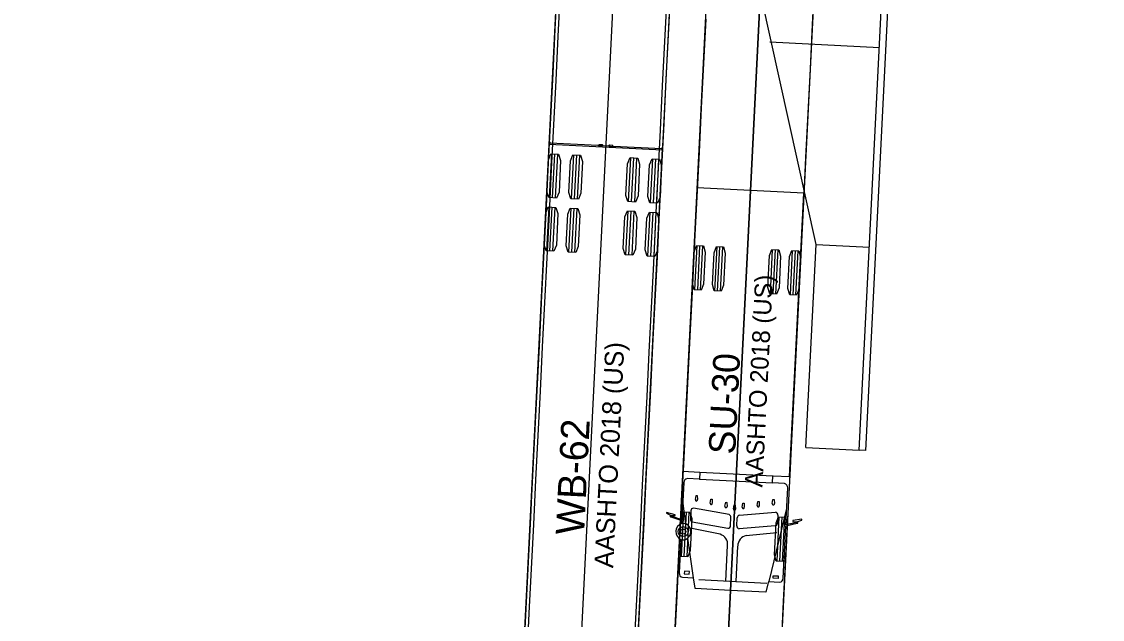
# Model space of a CAD drawing. Extents: x 260275 to 261282, y 610916 to 614143.
# Drawn here: x 260986.2 to 261067.3, y 611972 to 612016.8 of the extents above; entities that cross this region are included whole.
import ezdxf

# ---------------------------------------------------------------- set-up
doc = ezdxf.new("R2010")
doc.units = 0
for name, color, linetype in [('GE_X_Alignment', 7, 'Continuous'), ('PV_P_Curb', 7, 'Continuous'), ('PV_P_EOP', 7, 'Continuous'), ('PV_P_Joint', 7, 'Continuous'), ('UT_X_Water_Cells', 7, 'Continuous')]:
    doc.layers.add(name, color=color, linetype=linetype)

msp = doc.modelspace()

# ---------------------------------------------------------------- linework, layer by layer
at = {"layer": 'GE_X_Alignment'}
msp.add_line((260986.249, 610915.954), (261148.276, 614142.838), dxfattribs=at)
at = {"layer": 'PV_P_Curb'}
for p, q in [((261049.53, 611984.642), (261053.627, 612066.228)), ((261049.53, 611984.641), (261049.031, 611984.667))]:
    msp.add_line(p, q, dxfattribs=at)
at = {"layer": 'PV_P_EOP'}
for p, q in [((261045.801, 612000.096), (261031.212, 612066.209)), ((261049.031, 611984.667), (261053.122, 612066.147)), ((261045.036, 611984.867), (261045.801, 612000.096)), ((261045.036, 611984.867), (261049.031, 611984.667))]:
    msp.add_line(p, q, dxfattribs=at)
at = {"layer": 'PV_P_Joint'}
for p, q in [((261042.339, 612015.289), (261050.548, 612014.877)), ((261045.801, 612000.096), (261049.796, 611999.896))]:
    msp.add_line(p, q, dxfattribs=at)
at = {"layer": 'UT_X_Water_Cells'}
for p, q in [((261044.031, 612066.726), (261023.69, 611661.632)), ((261031.95, 612045.486), (261010.925, 611626.741)), ((261025.794, 612007.621), (261034.283, 612007.195)), ((261025.822, 612003.606), (261025.987, 612006.901)), ((261026.051, 612003.594), (261026.216, 612006.89)), ((261026.279, 612003.583), (261026.445, 612006.878)), ((261029.511, 612007.505), (261029.777, 612007.492)), ((261030.301, 612007.465), (261029.779, 612007.491)), ((261030.042, 612007.478), (261030.039, 612007.408)), ((261030.307, 612007.465), (261030.573, 612007.452)), ((261027.47, 612003.523), (261027.635, 612006.819)), ((261027.699, 612003.511), (261027.864, 612006.807)), ((261027.927, 612003.5), (261028.093, 612006.796)), ((261031.748, 612003.308), (261031.913, 612006.604)), ((261031.976, 612003.297), (261032.142, 612006.592)), ((261032.205, 612003.285), (261032.371, 612006.581)), ((261033.395, 612003.225), (261033.561, 612006.521)), ((261033.624, 612003.214), (261033.79, 612006.51)), ((261033.853, 612003.202), (261034.019, 612006.498)), ((261025.621, 611999.611), (261025.787, 612002.906)), ((261025.85, 611999.599), (261026.015, 612002.895)), ((261026.079, 611999.588), (261026.244, 612002.883)), ((261027.269, 611999.528), (261027.435, 612002.824)), ((261027.498, 611999.516), (261027.663, 612002.812)), ((261027.727, 611999.505), (261027.892, 612002.801)), ((261031.547, 611999.313), (261031.712, 612002.609)), ((261031.776, 611999.302), (261031.941, 612002.597)), ((261032.005, 611999.29), (261032.17, 612002.586)), ((261033.195, 611999.23), (261033.36, 612002.526)), ((261033.424, 611999.219), (261033.589, 612002.515)), ((261033.653, 611999.207), (261033.818, 612002.503)), ((261036.718, 611996.685), (261036.885, 612000.014)), ((261036.926, 611996.674), (261037.093, 612000.003)), ((261037.134, 611996.664), (261037.301, 611999.993)), ((261038.216, 611996.609), (261038.383, 611999.939)), ((261038.424, 611996.599), (261038.591, 611999.928)), ((261038.632, 611996.589), (261038.799, 611999.918)), ((261042.377, 611996.4), (261042.544, 611999.73)), ((261042.585, 611996.39), (261042.752, 611999.719)), ((261042.793, 611996.38), (261042.96, 611999.709)), ((261043.875, 611996.325), (261044.042, 611999.654)), ((261044.083, 611996.315), (261044.25, 611999.644)), ((261044.291, 611996.304), (261044.458, 611999.633)), ((261037.079, 611983.029), (261042.564, 611982.754)), ((261037.052, 611982.499), (261042.537, 611982.223)), ((261036.761, 611980.971), (261036.812, 611981.269)), ((261036.812, 611981.269), (261036.895, 611981.265)), ((261036.895, 611981.265), (261036.916, 611980.964)), ((261037.867, 611980.705), (261037.918, 611981.003)), ((261037.918, 611981.003), (261038, 611980.999)), ((261038, 611980.999), (261038.021, 611980.698)), ((261042.519, 611980.682), (261042.57, 611980.98)), ((261042.57, 611980.98), (261042.653, 611980.976)), ((261042.653, 611980.976), (261042.674, 611980.675)), ((261035.806, 611980.683), (261036.022, 611979.149)), ((261036.413, 611980.133), (261036.382, 611979.517)), ((261039.278, 611979.839), (261036.605, 611980.326)), ((261038.973, 611980.467), (261039.024, 611980.765)), ((261039.024, 611980.765), (261039.107, 611980.761)), ((261039.107, 611980.761), (261039.127, 611980.459)), ((261039.612, 611980.267), (261039.663, 611980.564)), ((261039.663, 611980.564), (261039.746, 611980.56)), ((261039.746, 611980.56), (261039.766, 611980.259)), ((261040.268, 611980.402), (261040.319, 611980.7)), ((261040.319, 611980.7), (261040.401, 611980.696)), ((261040.401, 611980.696), (261040.422, 611980.394)), ((261041.393, 611980.514), (261041.444, 611980.826)), ((261041.444, 611980.826), (261041.526, 611980.822)), ((261041.526, 611980.822), (261041.547, 611980.507)), ((261043.596, 611980.292), (261042.255, 611974.824)), ((261035.715, 611976.71), (261035.882, 611980.039)), ((261035.923, 611976.699), (261036.09, 611980.029)), ((261036.131, 611976.689), (261036.298, 611980.018)), ((261039.389, 611979.014), (261039.42, 611979.63)), ((261039.864, 611978.99), (261039.894, 611979.606)), ((261040.056, 611979.8), (261042.765, 611980.016)), ((261042.872, 611976.35), (261043.039, 611979.68)), ((261042.936, 611979.805), (261042.905, 611979.189)), ((261043.08, 611976.34), (261043.247, 611979.669)), ((261043.288, 611976.33), (261043.455, 611979.659)), ((261038.611, 611978.364), (261036.356, 611978.824)), ((261036.524, 611979.308), (261039.197, 611978.821)), ((261042.743, 611978.995), (261040.035, 611978.779)), ((261035.67, 611977.984), (261035.544, 611975.465)), ((261036.173, 611978.074), (261036.592, 611975.109)), ((261040.572, 611978.265), (261042.85, 611978.496)), ((261039.035, 611974.863), (261039.169, 611977.528)), ((261039.8, 611974.824), (261039.933, 611977.489)), ((261035.926, 611975.598), (261035.917, 611975.404)), ((261035.917, 611975.404), (261036.295, 611975.385)), ((261036.304, 611975.579), (261035.926, 611975.598)), ((261036.295, 611975.385), (261036.304, 611975.579)), ((261037.001, 611974.965), (261042.099, 611974.709)), ((261042.578, 611975.07), (261042.588, 611975.264)), ((261042.957, 611975.051), (261042.578, 611975.07)), ((261042.588, 611975.264), (261042.966, 611975.245)), ((261042.966, 611975.245), (261042.957, 611975.051))]:
    msp.add_line(p, q, dxfattribs=at)
for points in [[(261009.34, 611680.102), (261030.965, 612110.617), (261039.455, 612110.191), (261039.447, 612110.045), (261039.447, 612110.045)], [(261039.447, 612110.045), (261018.12, 611685.301)], [(261020.965, 611687.133), (261041.34, 612092.893), (261049.33, 612092.492), (261049.322, 612092.345), (261049.322, 612092.345)], [(261049.322, 612092.345), (261028.546, 611678.469)], [(261045.686, 612019.927), (261045.519, 612016.599), (261045.352, 612013.27), (261045.185, 612009.942), (261045.018, 612006.613), (261044.85, 612003.284), (261044.683, 611999.956), (261044.516, 611996.627), (261044.349, 611993.298), (261044.182, 611989.97), (261044.015, 611986.641), (261043.848, 611983.313), (261043.68, 611979.984), (261043.513, 611976.655), (261043.346, 611973.327), (261043.179, 611969.998)], [(261045.686, 612019.924), (261045.519, 612016.596), (261045.352, 612013.267), (261045.184, 612009.938), (261045.017, 612006.61), (261044.85, 612003.281), (261044.683, 611999.953), (261044.516, 611996.624), (261044.349, 611993.295), (261044.182, 611989.967), (261044.015, 611986.638), (261043.847, 611983.309), (261043.68, 611979.981), (261043.513, 611976.652), (261043.346, 611973.324), (261043.179, 611969.995)], [(261026.394, 612019.578), (261026.227, 612016.249), (261026.06, 612012.921), (261025.893, 612009.592), (261025.726, 612006.263), (261025.559, 612002.935), (261025.391, 611999.606), (261025.224, 611996.277), (261025.057, 611992.949), (261024.89, 611989.62), (261024.723, 611986.291), (261024.556, 611982.963), (261024.389, 611979.634), (261024.221, 611976.305), (261024.054, 611972.977), (261023.887, 611969.648)], [(261026.618, 612019.057), (261026.451, 612015.729), (261026.284, 612012.4), (261026.117, 612009.071), (261025.95, 612005.743), (261025.783, 612002.414), (261025.616, 611999.085), (261025.448, 611995.757), (261025.281, 611992.428), (261025.114, 611989.099), (261024.947, 611985.771), (261024.78, 611982.442), (261024.613, 611979.113), (261024.446, 611975.785), (261024.279, 611972.456), (261024.111, 611969.127)], [(261034.884, 612019.152), (261034.716, 612015.823), (261034.549, 612012.494), (261034.382, 612009.166), (261034.215, 612005.837), (261034.048, 612002.508), (261033.881, 611999.18), (261033.714, 611995.851), (261033.546, 611992.522), (261033.379, 611989.194), (261033.212, 611985.865), (261033.045, 611982.536), (261032.878, 611979.208), (261032.711, 611975.879), (261032.544, 611972.55), (261032.376, 611969.222)], [(261034.608, 612018.656), (261034.441, 612015.327), (261034.274, 612011.999), (261034.107, 612008.67), (261033.94, 612005.341), (261033.773, 612002.013), (261033.606, 611998.684), (261033.438, 611995.355), (261033.271, 611992.027), (261033.104, 611988.698), (261032.937, 611985.369), (261032.77, 611982.041), (261032.603, 611978.712), (261032.436, 611975.384), (261032.268, 611972.055), (261032.101, 611968.726)], [(261037.529, 612017), (261037.362, 612013.671), (261037.195, 612010.343), (261037.028, 612007.014), (261036.86, 612003.685), (261036.693, 612000.357), (261036.526, 611997.028), (261036.359, 611993.7), (261036.192, 611990.371), (261036.025, 611987.042), (261035.858, 611983.714), (261035.69, 611980.385), (261035.523, 611977.056), (261035.356, 611973.728), (261035.189, 611970.399)], [(261037.529, 612016.997), (261037.362, 612013.668), (261037.195, 612010.34), (261037.027, 612007.011), (261036.86, 612003.682), (261036.693, 612000.354), (261036.526, 611997.025), (261036.359, 611993.696), (261036.192, 611990.368), (261036.025, 611987.039), (261035.857, 611983.711), (261035.69, 611980.382), (261035.523, 611977.053), (261035.356, 611973.725), (261035.189, 611970.396)], [(261025.82, 612007.69), (261025.797, 612007.691), (261023.394, 611959.822), (261027.638, 611959.609), (261031.883, 611959.396), (261034.287, 612007.265), (261034.264, 612007.266)], [(261029.782, 612007.562), (261029.516, 612007.575), (261029.515, 612007.575), (261029.511, 612007.505), (261029.476, 612007.507), (261025.845, 612007.689), (261025.844, 612007.689)], [(261034.24, 612007.268), (261034.239, 612007.267), (261030.608, 612007.45), (261030.573, 612007.452), (261030.576, 612007.522), (261030.575, 612007.522), (261030.309, 612007.535)], [(261043.435, 611982.178), (261042.54, 611982.223), (261042.537, 611982.227), (261042.564, 611982.753), (261042.575, 611982.753), (261043.816, 611982.691), (261044.884, 612003.951), (261040.889, 612004.152), (261036.894, 612004.352), (261035.826, 611983.092), (261037.068, 611983.03), (261037.079, 611983.029), (261037.052, 611982.502), (261037.049, 611982.499), (261036.154, 611982.544)], [(261035.884, 611982.241), (261035.745, 611979.471), (261035.739, 611979.459), (261034.934, 611979.719), (261034.934, 611979.719)], [(261044.367, 611979.246), (261044.366, 611979.246), (261043.539, 611979.067), (261043.535, 611979.08), (261043.674, 611981.85)], [(261034.924, 611979.74), (261034.925, 611979.784), (261034.926, 611979.785), (261035.243, 611979.777), (261035.246, 611979.777), (261035.249, 611979.833), (261035.246, 611979.834), (261034.597, 611980.006), (261034.595, 611980.007), (261034.591, 611979.942), (261034.879, 611979.795), (261034.88, 611979.795), (261034.878, 611979.748)], [(261034.915, 611979.673), (261034.916, 611979.673), (261035.735, 611979.405), (261035.741, 611979.393), (261035.729, 611979.165)], [(261044.425, 611979.268), (261044.428, 611979.315), (261044.428, 611979.316), (261044.73, 611979.433), (261044.733, 611979.497), (261044.73, 611979.497), (261044.068, 611979.391), (261044.065, 611979.39), (261044.062, 611979.335), (261044.065, 611979.334), (261044.381, 611979.31), (261044.382, 611979.309), (261044.379, 611979.265)], [(261043.334, 611975.074), (261043.531, 611979.002), (261043.538, 611979.013), (261044.38, 611979.198), (261044.381, 611979.197)], [(261035.782, 611975.149), (261036.588, 611975.109), (261036.592, 611975.104), (261036.702, 611974.326), (261036.744, 611974.322), (261039.384, 611974.189), (261042.025, 611974.057), (261042.067, 611974.057), (261042.254, 611974.82), (261042.259, 611974.824), (261043.065, 611974.784)]]:
    msp.add_lwpolyline(points, dxfattribs=at)
for points in [[(261026.336, 612003.58), (261025.765, 612003.608), (261025.616, 612004.078), (261025.735, 612006.451), (261025.93, 612006.904), (261026.502, 612006.876), (261026.651, 612006.405), (261026.532, 612004.032)], [(261027.984, 612003.497), (261027.413, 612003.526), (261027.264, 612003.996), (261027.383, 612006.369), (261027.578, 612006.821), (261028.15, 612006.793), (261028.299, 612006.323), (261028.179, 612003.95)], [(261032.262, 612003.282), (261031.691, 612003.311), (261031.542, 612003.781), (261031.661, 612006.154), (261031.856, 612006.607), (261032.428, 612006.578), (261032.577, 612006.108), (261032.457, 612003.735)], [(261033.91, 612003.199), (261033.339, 612003.228), (261033.19, 612003.698), (261033.309, 612006.071), (261033.504, 612006.524), (261034.076, 612006.495), (261034.224, 612006.025), (261034.105, 612003.652)], [(261026.136, 611999.585), (261025.564, 611999.613), (261025.415, 612000.083), (261025.535, 612002.456), (261025.73, 612002.909), (261026.301, 612002.881), (261026.45, 612002.411), (261026.331, 612000.038)], [(261027.784, 611999.502), (261027.212, 611999.531), (261027.063, 612000.001), (261027.182, 612002.374), (261027.378, 612002.827), (261027.949, 612002.798), (261028.098, 612002.328), (261027.979, 611999.955)], [(261032.061, 611999.287), (261031.49, 611999.316), (261031.341, 611999.786), (261031.46, 612002.159), (261031.656, 612002.612), (261032.227, 612002.583), (261032.376, 612002.113), (261032.257, 611999.74)], [(261033.709, 611999.204), (261033.138, 611999.233), (261032.989, 611999.703), (261033.108, 612002.076), (261033.304, 612002.529), (261033.875, 612002.5), (261034.024, 612002.03), (261033.905, 611999.657)], [(261037.185, 611996.661), (261036.666, 611996.687), (261036.533, 611997.161), (261036.653, 611999.558), (261036.833, 612000.016), (261037.352, 611999.99), (261037.485, 611999.516), (261037.365, 611997.119)], [(261038.683, 611996.586), (261038.164, 611996.612), (261038.031, 611997.086), (261038.151, 611999.483), (261038.331, 611999.941), (261038.851, 611999.915), (261038.984, 611999.441), (261038.863, 611997.044)], [(261042.845, 611996.377), (261042.325, 611996.403), (261042.192, 611996.877), (261042.313, 611999.274), (261042.493, 611999.732), (261043.012, 611999.706), (261043.145, 611999.232), (261043.025, 611996.835)], [(261044.343, 611996.302), (261043.824, 611996.328), (261043.69, 611996.802), (261043.811, 611999.199), (261043.991, 611999.657), (261044.51, 611999.631), (261044.643, 611999.157), (261044.523, 611996.76)], [(261036.182, 611976.686), (261035.663, 611976.712), (261035.53, 611977.186), (261035.65, 611979.583), (261035.83, 611980.042), (261036.349, 611980.015), (261036.483, 611979.542), (261036.362, 611977.145)], [(261043.34, 611976.327), (261042.821, 611976.353), (261042.688, 611976.827), (261042.808, 611979.224), (261042.988, 611979.682), (261043.507, 611979.656), (261043.64, 611979.182), (261043.52, 611976.785)]]:
    msp.add_lwpolyline(points, close=True, dxfattribs=at)
for centre, radius in [((261025.833, 612007.724), 0.0266), ((261034.254, 612007.301), 0.0266), ((261035.845, 611978.567), 0.374), ((261035.845, 611978.567), 0.193)]:
    msp.add_circle(centre, radius, dxfattribs=at)
for centre, radius, start, end in [((261025.833, 612007.724), 0.0363, 286.88607, 248.0487), ((261029.781, 612007.527), 0.0354, 91.41704, 263.6025), ((261029.781, 612007.527), 0.0352, 266.52344, 87.10992), ((261030.307, 612007.5), 0.0352, 87.14108, 267.72757), ((261030.307, 612007.5), 0.0352, 266.91304, 89.55244), ((261034.254, 612007.301), 0.0363, 286.20231, 247.36494), ((261036.206, 611982.225), 0.323, 99.2771, 177.1255), ((261043.352, 611981.866), 0.323, 357.1255, 74.97391), ((261036.849, 611980.949), 0.091, 165.44206, 259.60593), ((261036.826, 611980.95), 0.0909, 274.60942, 8.84462), ((261036.598, 611980.141), 0.184, 87.71808, 182.58934), ((261037.955, 611980.682), 0.091, 165.44206, 259.60593), ((261037.931, 611980.684), 0.0909, 274.60942, 8.84462), ((261039.061, 611980.444), 0.091, 165.44206, 259.60593), ((261039.038, 611980.445), 0.0909, 274.60942, 8.84462), ((261039.7, 611980.244), 0.091, 165.44206, 259.60593), ((261039.677, 611980.245), 0.091, 274.64508, 8.80895), ((261040.356, 611980.379), 0.0909, 165.40639, 259.64159), ((261040.332, 611980.38), 0.091, 274.64508, 8.80895), ((261041.481, 611980.505), 0.0909, 165.40639, 259.64159), ((261041.457, 611980.507), 0.091, 274.64508, 8.80895), ((261042.607, 611980.659), 0.0909, 165.40639, 259.64159), ((261042.584, 611980.661), 0.091, 274.64508, 8.80895), ((261034.897, 611979.711), 0.0418, 117.61865, 294.63358), ((261034.891, 611979.711), 0.0434, 11.03902, 41.7118), ((261036.574, 611979.494), 0.193, 173.06859, 254.98308), ((261039.228, 611979.653), 0.193, 353.06366, 74.98801), ((261040.087, 611979.61), 0.193, 99.26299, 181.18734), ((261042.753, 611979.832), 0.184, 351.66167, 86.53293), ((261035.912, 611978.564), 0.628, 106.8788, 247.3705), ((261035.849, 611978.654), 0.524, 49.38452, 103.18459), ((261035.776, 611978.562), 0.629, 309.17109, 357.86038), ((261035.776, 611978.578), 0.63, 356.4803, 48.88311), ((261039.204, 611979.006), 0.184, 267.72364, 2.58377), ((261040.046, 611978.963), 0.184, 171.66723, 266.52737), ((261042.712, 611979.186), 0.193, 279.26792, 1.18241), ((261044.408, 611979.233), 0.0434, 132.53921, 163.21198), ((261044.402, 611979.234), 0.0418, 239.61742, 56.63235), ((261035.841, 611978.481), 0.526, 251.07067, 309.31667), ((261038.401, 611977.62), 0.773, 353.15088, 74.23504), ((261040.706, 611977.504), 0.773, 100.01597, 181.10013), ((261035.823, 611975.428), 0.282, 172.49767, 261.5771), ((261043.052, 611975.065), 0.282, 272.67391, 1.75333)]:
    msp.add_arc(centre, radius, start, end, dxfattribs=at)

# ---------------------------------------------------------------- texts
for s, height, p in [('AASHTO 2018 (US)', 1.33333, (261041.779, 611981.865)), ('AASHTO 2018 (US)', 1.41667, (261030.587, 611975.816)), ('SU-30', 2, (261039.733, 611984.327)), ('WB-62', 2.125, (261028.406, 611978.282))]:
    msp.add_text(s, height=height, rotation=87.1255, dxfattribs=at).set_placement(p)

doc.saveas('drawing.dxf')
